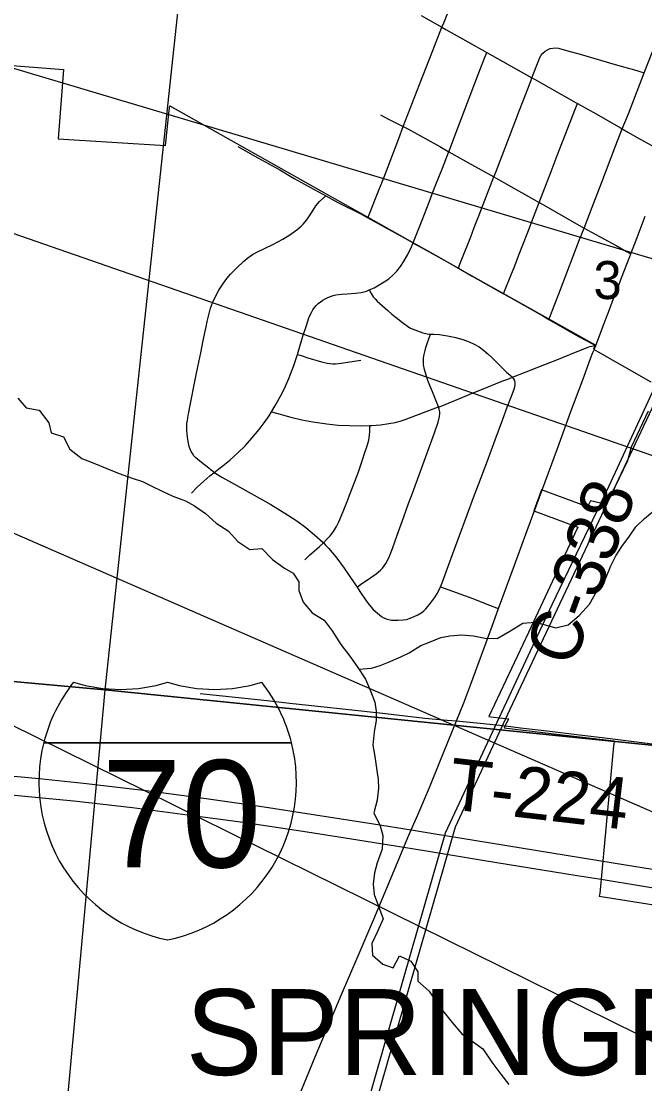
# Model space of a CAD drawing. Extents: x 0 to 34, y 0 to 22.
# Drawn here: x 7.893 to 8.581, y 15.624 to 16.796 of the extents above; entities that cross this region are included whole.
import ezdxf

# ---------------------------------------------------------------- set-up
doc = ezdxf.new("R2010")
doc.units = 0
for name, color, linetype in [('Default', 7, 'Continuous'), ('GM_X_City_Street', 7, 'Continuous'), ('GM_X_Corporation_Text', 7, 'Continuous'), ('GM_X_County_Road', 7, 'Continuous'), ('GM_X_County_Road_Text', 7, 'Continuous'), ('GM_X_Interstate_Location', 7, 'Continuous'), ('GM_X_Interstate_Route', 7, 'Continuous'), ('GM_X_Interstate_Shield', 7, 'Continuous'), ('GM_X_Minor_River', 7, 'Continuous'), ('GM_X_Rail_Line', 7, 'Continuous'), ('GM_X_Section', 7, 'Continuous'), ('GM_X_Section_Text', 7, 'Continuous'), ('GM_X_Township_Road', 7, 'Continuous'), ('GM_X_Township_Road_Text', 7, 'Continuous'), ('SC_Shading1', 7, 'Continuous'), ('SH_Text', 7, 'Continuous')]:
    doc.layers.add(name, color=color, linetype=linetype)

msp = doc.modelspace()

# ---------------------------------------------------------------- linework, layer by layer
at = {"layer": 'Default'}
for points in [[(8.9, 15.9657), (8.9, 17.0075), (8.0956, 17.09), (7.9848, 16.0585)], [(8.9, 14.9629), (8.9, 15.9657), (7.9848, 16.0585), (7.893, 15.0559), (8.8988, 14.9496)]]:
    msp.add_lwpolyline(points, close=True, dxfattribs=at)
at = {"layer": 'GM_X_City_Street'}
for points in [[(8.4747, 16.467), (8.4764, 16.4712), (8.4787, 16.477), (8.4876, 16.5001), (8.5087, 16.5551), (8.5136, 16.5677), (8.5177, 16.5782), (8.5243, 16.5955), (8.533, 16.6184), (8.5487, 16.6592), (8.5557, 16.677), (8.5624, 16.6938), (8.58, 16.739), (8.5893, 16.7631), (8.5993, 16.7891), (8.6027, 16.7971), (8.6074, 16.809), (8.6105, 16.8175), (8.6122, 16.8234), (8.6135, 16.8294), (8.6139, 16.8323), (8.6146, 16.8413), (8.6154, 16.8504), (8.616, 16.8562)], [(8.2752, 16.5791), (8.2768, 16.5832), (8.2837, 16.6003), (8.2927, 16.6231), (8.3004, 16.6433), (8.3093, 16.6665), (8.3142, 16.6795), (8.3244, 16.7063), (8.3322, 16.7261), (8.3466, 16.7635), (8.3568, 16.7893), (8.3591, 16.7947), (8.3627, 16.8031), (8.3654, 16.8086), (8.3701, 16.8163), (8.3737, 16.8212), (8.3776, 16.8258), (8.3819, 16.8301), (8.3856, 16.8334), (8.3882, 16.8354), (8.3896, 16.8365), (8.391, 16.8372), (8.3922, 16.8375)], [(8.3339, 16.8022), (8.3568, 16.7893), (8.361, 16.7868), (8.3855, 16.7731), (8.4062, 16.7614), (8.4561, 16.7332), (8.4588, 16.7317), (8.5049, 16.7056), (8.5063, 16.7049), (8.5268, 16.6935), (8.5538, 16.6781), (8.5557, 16.677), (8.562, 16.6735), (8.5755, 16.6657), (8.5916, 16.6569), (8.595, 16.6551), (8.598, 16.6535), (8.601, 16.6518), (8.607, 16.6485)], [(8.3749, 16.5234), (8.3767, 16.5278), (8.3824, 16.5426), (8.3849, 16.5488), (8.3885, 16.5581), (8.3924, 16.5682), (8.3974, 16.581), (8.4004, 16.5887), (8.4142, 16.6241), (8.4163, 16.6293), (8.4314, 16.6687), (8.4425, 16.6977), (8.4547, 16.7295), (8.4561, 16.7332), (8.4635, 16.7528), (8.4648, 16.7556), (8.4662, 16.7583), (8.4682, 16.7607), (8.4706, 16.7627), (8.4732, 16.7643), (8.4761, 16.7655), (8.4791, 16.7661), (8.4822, 16.7663), (8.4853, 16.766), (8.4943, 16.7636), (8.5092, 16.7593), (8.548, 16.7482), (8.5719, 16.7413), (8.5749, 16.7404), (8.58, 16.739)], [(8.3251, 16.5514), (8.327, 16.5562), (8.3351, 16.5762), (8.3426, 16.5962), (8.3457, 16.6044), (8.3493, 16.6137), (8.3573, 16.6338), (8.3641, 16.6511), (8.3644, 16.6518), (8.375, 16.6801), (8.3949, 16.7322), (8.4037, 16.7551), (8.4062, 16.7614)], [(8.4248, 16.4953), (8.4266, 16.4998), (8.4329, 16.5154), (8.4371, 16.526), (8.4413, 16.5371), (8.446, 16.5491), (8.4514, 16.5631), (8.4597, 16.5844), (8.4642, 16.596), (8.4774, 16.6302), (8.4839, 16.6476), (8.5042, 16.6994), (8.5063, 16.7049)], [(8.289, 16.6926), (8.297, 16.6881), (8.3081, 16.6826), (8.3142, 16.6795), (8.3191, 16.677), (8.3543, 16.6575), (8.3644, 16.6518), (8.3895, 16.6379), (8.4142, 16.6241), (8.4166, 16.6228), (8.4642, 16.596), (8.4688, 16.5934), (8.5054, 16.5723), (8.5136, 16.5677), (8.5216, 16.5632), (8.5489, 16.5483), (8.5604, 16.5419), (8.5652, 16.5394)]]:
    msp.add_lwpolyline(points, dxfattribs=at)
at = {"layer": 'GM_X_County_Road'}
msp.add_line((8.5234, 16.4305), (8.5246, 16.4334), dxfattribs=at)
for points in [[(8.5652, 16.5394), (8.5721, 16.5574), (8.5811, 16.5808)], [(8.5264, 16.4381), (8.5373, 16.4666), (8.5415, 16.4778), (8.5462, 16.49), (8.5508, 16.5018), (8.555, 16.5129), (8.5641, 16.5364), (8.5652, 16.5394)], [(8.4193, 16.1481), (8.4229, 16.1581), (8.4369, 16.196), (8.4507, 16.2341), (8.4842, 16.3245), (8.4991, 16.3654), (8.5121, 16.4004), (8.5207, 16.4238), (8.5234, 16.4305)], [(8.5246, 16.4334), (8.5255, 16.4357), (8.5264, 16.4381)], [(8.373, 16.0241), (8.3808, 16.0443), (8.3886, 16.0646), (8.4123, 16.1288), (8.4193, 16.1481)], [(8.2816, 15.8055), (8.3079, 15.8679), (8.3149, 15.8849), (8.3193, 15.8955), (8.323, 15.904), (8.3303, 15.9207), (8.3431, 15.9506), (8.3545, 15.9791), (8.373, 16.0241)], [(8.1707, 15.5377), (8.1766, 15.553), (8.1914, 15.5905), (8.1994, 15.6107), (8.217, 15.6538), (8.246, 15.7225), (8.2645, 15.7652), (8.2816, 15.8055)]]:
    msp.add_lwpolyline(points, dxfattribs=at)
at = {"layer": 'GM_X_Interstate_Route'}
for points in [[(7.8568, 15.966), (7.9124, 15.9606), (7.9613, 15.9556), (8.0305, 15.9476), (8.0943, 15.9389), (8.1559, 15.9303), (8.2172, 15.9208), (8.2813, 15.9108), (8.323, 15.904), (8.347, 15.9002), (8.4104, 15.8897), (8.5456, 15.8678), (8.6624, 15.8489), (8.7176, 15.8399), (8.8158, 15.824), (8.8737, 15.8145), (8.9, 15.8102)], [(7.7421, 15.9546), (7.777, 15.952), (7.8186, 15.949), (7.9003, 15.941), (7.9508, 15.936), (8.0154, 15.9286), (8.0761, 15.9208), (8.1375, 15.9124), (8.208, 15.902), (8.257, 15.8941), (8.3149, 15.8849), (8.3397, 15.8809), (8.4036, 15.8703), (8.5061, 15.8539), (8.5347, 15.8492)], [(8.5347, 15.8492), (8.7351, 15.8161), (8.8796, 15.7931), (8.9, 15.7898)]]:
    msp.add_lwpolyline(points, dxfattribs=at)
at = {"layer": 'GM_X_Interstate_Shield'}
for p, q in [((7.9176, 16.0002), (8.1909, 16.0002)), ((8.1909, 16.0002), (7.9176, 16.0002)), ((8.1909, 16.0002), (7.9176, 16.0002))]:
    msp.add_line(p, q, dxfattribs=at)
for centre, start, end in [((8.0898, 15.9567), 141.669, 165.8066), ((8.0024, 16.2366), 253.0091, 286.9909), ((8.1061, 16.2366), 253.0091, 286.9909), ((8.0187, 15.9567), 14.1934, 38.331), ((8.0898, 15.9567), 165.8066, 258.463), ((8.0187, 15.9567), 281.537, 14.1934)]:
    msp.add_arc(centre, 0.1776, start, end, dxfattribs=at)
at = {"layer": 'GM_X_Minor_River'}
for points in [[(7.889, 16.3801), (7.8983, 16.3694), (7.9127, 16.367), (7.9232, 16.3529), (7.9258, 16.3419), (7.9393, 16.3376), (7.9464, 16.3239), (7.9596, 16.3136), (7.9728, 16.3085), (7.9871, 16.3024), (8.0007, 16.297), (8.015, 16.2919), (8.0267, 16.2881), (8.0369, 16.283), (8.0475, 16.278), (8.0599, 16.2719), (8.0739, 16.2668), (8.0837, 16.2615), (8.0961, 16.253), (8.1077, 16.2423), (8.1209, 16.2339), (8.1318, 16.2221), (8.145, 16.2132), (8.1582, 16.2143), (8.1698, 16.2021), (8.183, 16.1925), (8.1928, 16.1871), (8.1988, 16.1776), (8.1991, 16.1681), (8.2039, 16.1552), (8.2137, 16.1434), (8.2268, 16.1353), (8.2358, 16.1235), (8.2452, 16.1086), (8.2553, 16.0957), (8.2639, 16.0831), (8.2725, 16.0701), (8.2781, 16.0572), (8.2829, 16.045), (8.2843, 16.0348), (8.2843, 16.0245), (8.2819, 16.012), (8.2807, 15.9976), (8.2828, 15.9851), (8.285, 15.9696), (8.2864, 15.9597), (8.2867, 15.9502), (8.2855, 15.9369), (8.2816, 15.923), (8.2887, 15.9085), (8.2916, 15.8979), (8.2908, 15.8827), (8.2854, 15.8676), (8.2826, 15.8566), (8.281, 15.8441), (8.2821, 15.8327)], [(8.2651, 16.0813), (8.279, 16.0822), (8.2885, 16.0852), (8.298, 16.0889), (8.3113, 16.0949), (8.3208, 16.0993), (8.3337, 16.1072), (8.3432, 16.1109), (8.3557, 16.1161), (8.3655, 16.118), (8.3784, 16.119), (8.3916, 16.1181), (8.4045, 16.1154), (8.4177, 16.1149), (8.4318, 16.1232), (8.4459, 16.1321), (8.4595, 16.1332), (8.4693, 16.1305), (8.4825, 16.1269), (8.4961, 16.1303), (8.5083, 16.1404), (8.5194, 16.1528), (8.5278, 16.1672), (8.5374, 16.1815), (8.5432, 16.1951), (8.5485, 16.2061), (8.5554, 16.2166), (8.5635, 16.2279), (8.5707, 16.2381), (8.5802, 16.2475), (8.5928, 16.2577)], [(8.2821, 15.8327), (8.2869, 15.8198), (8.2921, 15.8061), (8.2856, 15.7921), (8.2794, 15.7789), (8.2801, 15.766), (8.2917, 15.7561), (8.303, 15.7518), (8.3099, 15.765), (8.3224, 15.7592), (8.3302, 15.7474), (8.3302, 15.7372), (8.3426, 15.7261), (8.35, 15.7151), (8.3579, 15.7044), (8.368, 15.6918), (8.3789, 15.6792), (8.3887, 15.6723), (8.4019, 15.6627), (8.412, 15.6479), (8.4217, 15.6345), (8.4307, 15.6231)]]:
    msp.add_lwpolyline(points, dxfattribs=at)
at = {"layer": 'GM_X_Rail_Line'}
for points in [[(7.2798, 14.1), (7.3804, 14.2899), (7.4399, 14.3809), (7.5029, 14.451), (7.5671, 14.514), (7.6729, 14.6161), (7.8627, 14.7836), (7.9234, 14.8447), (7.9746, 14.9008), (8.0463, 14.9864), (8.1054, 15.083), (8.1652, 15.2252), (8.1826, 15.274), (8.2135, 15.3861), (8.2835, 15.6324), (8.3606, 15.9006), (8.4204, 16.0285), (8.4785, 16.1527), (8.5411, 16.2834), (8.5955, 16.4012), (8.7466, 16.719), (8.8431, 16.9243), (8.9, 17.0477)], [(8.6715, 16.5448), (8.4316, 16.0366), (8.3713, 15.9072), (8.1815, 15.2486), (8.1107, 15.0795), (8.0486, 14.9789), (7.9789, 14.8968), (7.9015, 14.815), (7.882, 14.794), (7.8474, 14.7064), (7.8234, 14.6409), (7.725, 14.3971), (7.6108, 14.1)]]:
    msp.add_lwpolyline(points, dxfattribs=at)
at = {"layer": 'GM_X_Section'}
for points in [[(7.0855, 17.1656), (8.0956, 17.09), (7.9848, 16.0585), (6.992, 16.1486)], [(6.992, 16.1486), (7.9848, 16.0585), (7.893, 15.0559), (6.9002, 15.1449)]]:
    msp.add_lwpolyline(points, close=True, dxfattribs=at)
at = {"layer": 'GM_X_Township_Road'}
for points in [[(8.1317, 16.6576), (8.1403, 16.6527), (8.1536, 16.645), (8.178, 16.6318), (8.1939, 16.6225), (8.2127, 16.6119), (8.2286, 16.6032)], [(8.1057, 16.2982), (8.1049, 16.2988), (8.1023, 16.3007), (8.0997, 16.3028), (8.0915, 16.309), (8.0877, 16.3123), (8.0853, 16.3144), (8.0832, 16.3166), (8.0816, 16.319), (8.0802, 16.3212), (8.0791, 16.3238), (8.0781, 16.3267), (8.0773, 16.3304), (8.0765, 16.3346), (8.0759, 16.3399), (8.0754, 16.3453), (8.0754, 16.3492), (8.0756, 16.3523), (8.076, 16.3554), (8.0769, 16.3615), (8.0775, 16.3644), (8.0787, 16.3705), (8.0855, 16.404), (8.0877, 16.4148), (8.0907, 16.4301), (8.0934, 16.4435), (8.0967, 16.4586), (8.098, 16.4646), (8.1, 16.4736), (8.1017, 16.4795), (8.1039, 16.4853), (8.1064, 16.4909), (8.1108, 16.4991), (8.1158, 16.507), (8.1195, 16.512), (8.1235, 16.5167), (8.1302, 16.5235), (8.1384, 16.5312), (8.1426, 16.5347), (8.1467, 16.5376), (8.1487, 16.539), (8.1533, 16.5416), (8.1701, 16.5497), (8.1812, 16.5554), (8.1892, 16.5602), (8.1967, 16.5656), (8.2015, 16.5696), (8.2037, 16.5718), (8.2076, 16.5767), (8.2128, 16.5844), (8.2178, 16.5923), (8.2218, 16.5971), (8.2286, 16.6032)], [(8.2286, 16.6032), (8.2421, 16.596), (8.2667, 16.5837), (8.2752, 16.5791)], [(8.2752, 16.5791), (8.3126, 16.5584), (8.3251, 16.5514)], [(8.2766, 16.4994), (8.2822, 16.5019), (8.2877, 16.5049), (8.293, 16.5082), (8.2981, 16.5118), (8.3028, 16.5158), (8.3071, 16.5203), (8.311, 16.5251), (8.3144, 16.5303), (8.319, 16.5386), (8.3232, 16.5469), (8.3251, 16.5514)], [(8.3251, 16.5514), (8.3288, 16.5493), (8.3499, 16.5374), (8.3633, 16.5301), (8.3749, 16.5234)], [(8.3749, 16.5234), (8.3901, 16.5148), (8.4248, 16.4953)], [(8.1976, 16.4283), (8.2035, 16.4484), (8.2073, 16.4602), (8.2101, 16.4686), (8.2115, 16.4719), (8.2128, 16.4747), (8.2143, 16.4774), (8.2162, 16.48), (8.2182, 16.4823), (8.2204, 16.4845), (8.2228, 16.4865), (8.2254, 16.4882), (8.2281, 16.4898), (8.2309, 16.4912), (8.2338, 16.4923), (8.2367, 16.4932), (8.2398, 16.4939), (8.246, 16.4946), (8.2522, 16.4951), (8.2615, 16.496), (8.2676, 16.4967), (8.2707, 16.4973), (8.2737, 16.4981), (8.2766, 16.4994)], [(8.2766, 16.4994), (8.2787, 16.4956), (8.281, 16.492), (8.283, 16.4895), (8.2855, 16.4869), (8.2971, 16.4766), (8.3016, 16.4729), (8.3063, 16.4689), (8.3134, 16.4634), (8.3187, 16.4594), (8.3213, 16.4578), (8.3241, 16.4564), (8.3298, 16.4542), (8.3357, 16.4523), (8.3406, 16.4512), (8.3442, 16.4507)], [(8.4248, 16.4953), (8.4304, 16.4922), (8.4681, 16.4708), (8.4747, 16.467)], [(8.4747, 16.467), (8.4971, 16.4541), (8.5083, 16.4477), (8.5237, 16.4395), (8.5264, 16.4381)], [(8.3531, 16.3704), (8.3517, 16.3742), (8.3494, 16.3798), (8.3483, 16.3827), (8.3435, 16.394), (8.3413, 16.3997), (8.3393, 16.4056), (8.3377, 16.4116), (8.3366, 16.4168), (8.3364, 16.4208), (8.3365, 16.4237), (8.3369, 16.4268), (8.3382, 16.4328), (8.339, 16.4358), (8.3409, 16.4415), (8.3419, 16.4444), (8.3442, 16.4507)], [(8.3442, 16.4507), (8.3448, 16.4506), (8.3478, 16.4505), (8.354, 16.4502), (8.3631, 16.449), (8.3721, 16.4471), (8.381, 16.4445), (8.3868, 16.4423), (8.3924, 16.4398), (8.3977, 16.4366), (8.4027, 16.433), (8.4074, 16.429), (8.4119, 16.4248), (8.4229, 16.4138), (8.4279, 16.4089), (8.4319, 16.4054), (8.4346, 16.4031)], [(8.1688, 16.3651), (8.1726, 16.3713), (8.1801, 16.3849), (8.1843, 16.3933), (8.1881, 16.4018), (8.1936, 16.4162), (8.1976, 16.4283)], [(8.1976, 16.4283), (8.2027, 16.4267), (8.209, 16.4247), (8.224, 16.4202), (8.2302, 16.4187), (8.2333, 16.4182), (8.2364, 16.4179), (8.2395, 16.4179), (8.2458, 16.4186), (8.2675, 16.422)], [(8.4346, 16.4031), (8.4498, 16.4091), (8.4637, 16.4145), (8.4836, 16.4225), (8.5041, 16.4308), (8.5181, 16.4362), (8.5199, 16.4369), (8.522, 16.4374), (8.5235, 16.4377), (8.5264, 16.4381)], [(8.3531, 16.3704), (8.354, 16.3707), (8.3712, 16.3776), (8.3912, 16.3859), (8.3997, 16.3894), (8.424, 16.3991), (8.4294, 16.4011), (8.4346, 16.4031)], [(8.3551, 16.1721), (8.357, 16.1764), (8.3643, 16.1968), (8.3685, 16.2078), (8.3845, 16.2514), (8.3917, 16.2705), (8.3972, 16.2849), (8.4069, 16.3109), (8.4155, 16.334), (8.4238, 16.3569), (8.4288, 16.3701), (8.4344, 16.384), (8.4369, 16.3911), (8.4376, 16.3946), (8.4376, 16.3966), (8.4371, 16.3995), (8.4361, 16.4013), (8.4346, 16.4031)], [(8.2632, 16.1718), (8.2675, 16.1749), (8.2726, 16.1784), (8.2794, 16.1831), (8.2843, 16.1865), (8.289, 16.1905), (8.2911, 16.1928), (8.293, 16.1952), (8.2948, 16.1978), (8.2964, 16.2004), (8.299, 16.2058), (8.3024, 16.2143), (8.3075, 16.2289), (8.3147, 16.2493), (8.3199, 16.2638), (8.3242, 16.2754), (8.3327, 16.2985), (8.3402, 16.3188), (8.3486, 16.342), (8.3525, 16.3537), (8.3541, 16.3597), (8.3546, 16.3628), (8.3544, 16.3652), (8.3538, 16.3681), (8.3531, 16.3704)], [(8.2773, 16.35), (8.2796, 16.3501), (8.2889, 16.3508), (8.2981, 16.352), (8.3052, 16.3533), (8.3106, 16.3547), (8.3162, 16.3565), (8.3365, 16.3642), (8.3531, 16.3704)], [(8.1057, 16.2982), (8.1069, 16.2991), (8.1106, 16.302), (8.1155, 16.3058), (8.1227, 16.3118), (8.1315, 16.3198), (8.1396, 16.3276), (8.1471, 16.336), (8.1551, 16.3454), (8.1608, 16.3529), (8.1661, 16.3606), (8.1688, 16.3651)], [(8.1688, 16.3651), (8.1783, 16.3624), (8.1902, 16.359), (8.2023, 16.3562), (8.2145, 16.3539), (8.2299, 16.3517), (8.2423, 16.3505), (8.2547, 16.3498), (8.2672, 16.3497), (8.2773, 16.35)], [(8.226, 16.2207), (8.2302, 16.2249), (8.2337, 16.2284), (8.2372, 16.2331), (8.2404, 16.2384), (8.2431, 16.2439), (8.248, 16.2553), (8.2529, 16.2679), (8.2549, 16.2733), (8.2606, 16.2882), (8.2643, 16.2978), (8.2695, 16.3131), (8.2715, 16.319), (8.2745, 16.3277), (8.2761, 16.3337), (8.2767, 16.3367), (8.277, 16.3397), (8.2771, 16.3425), (8.2773, 16.35)], [(8.0806, 16.2754), (8.087, 16.2821), (8.0942, 16.2886), (8.1009, 16.2943), (8.1057, 16.2982)], [(8.1057, 16.2982), (8.1142, 16.2931), (8.1248, 16.2871), (8.1679, 16.263), (8.1863, 16.2516), (8.1966, 16.2447), (8.2066, 16.2373), (8.2162, 16.2295), (8.2254, 16.2213), (8.226, 16.2207)], [(8.2056, 16.202), (8.2109, 16.2068), (8.2218, 16.2167), (8.226, 16.2207)], [(8.226, 16.2207), (8.2288, 16.2178), (8.2318, 16.2146), (8.2396, 16.205), (8.249, 16.1927), (8.2561, 16.1825), (8.2632, 16.1718)], [(8.2632, 16.1718), (8.2663, 16.167), (8.2732, 16.1567), (8.277, 16.1518), (8.2811, 16.1471), (8.2856, 16.1429), (8.2879, 16.141), (8.2903, 16.1394), (8.2927, 16.1379), (8.2954, 16.1368), (8.2984, 16.1359), (8.301, 16.1354), (8.3037, 16.1352), (8.3084, 16.1352), (8.314, 16.1357), (8.3177, 16.1362), (8.3216, 16.1374), (8.3262, 16.1392), (8.3303, 16.1412), (8.3345, 16.1438), (8.3369, 16.1457), (8.3391, 16.1477), (8.3431, 16.1524), (8.3485, 16.16), (8.3518, 16.1652), (8.3546, 16.1707), (8.3551, 16.1721)], [(8.3551, 16.1721), (8.3592, 16.1706), (8.3907, 16.159), (8.4026, 16.1545), (8.4094, 16.1519), (8.4169, 16.149), (8.4193, 16.1481)], [(8.0902, 16.0546), (8.1642, 16.0467), (8.189, 16.0439), (8.22, 16.0406), (8.2541, 16.0368), (8.2944, 16.0323), (8.3378, 16.0272), (8.3625, 16.025), (8.373, 16.0241)], [(8.373, 16.0241), (8.3876, 16.0229), (8.3988, 16.0217), (8.4271, 16.0186), (8.4436, 16.0167), (8.4759, 16.0128), (8.5056, 16.0091), (8.5363, 16.0054), (8.6003, 15.9975), (8.6013, 15.9974)]]:
    msp.add_lwpolyline(points, dxfattribs=at)
at = {"layer": 'SC_Shading1'}
for points in [[(7.8732, 16.7475), (7.9395, 16.7425), (7.9334, 16.6662), (8.052, 16.6588), (8.056, 16.6972), (8.0565, 16.7023), (8.229, 16.6054), (8.2749, 16.5796), (8.3247, 16.5517), (8.3248, 16.5516), (8.3531, 16.5358), (8.3746, 16.5236), (8.5258, 16.4388), (8.524, 16.4341), (8.529, 16.4313), (8.5872, 16.398)], [(8.5844, 16.3657), (8.5655, 16.3261), (8.5616, 16.3109), (8.5384, 16.2628), (8.5205, 16.267), (8.5173, 16.2603), (8.4667, 16.279), (8.4582, 16.2559), (8.5067, 16.238), (8.4866, 16.195), (8.4521, 16.1216), (8.4085, 16.0289), (8.4135, 16.0284), (8.4205, 16.0276), (8.4304, 16.0266), (8.4255, 16.0164), (8.4893, 16.009), (8.4931, 16.0086), (8.5467, 16.0023), (8.5463, 15.9986), (8.5461, 15.9967), (8.5361, 15.8899), (8.5308, 15.834), (8.5303, 15.8311), (8.8452, 15.7811)]]:
    msp.add_lwpolyline(points, dxfattribs=at)
at = {"layer": 'SH_Text'}
for points in [[(9.3277, 15.6016), (4.1983, 17.8389), (9.3277, 15.3062)], [(9.3042, 16.3207), (4.2062, 17.84), (9.3042, 16.0683)]]:
    msp.add_lwpolyline(points, close=True, dxfattribs=at)

# ---------------------------------------------------------------- texts
at = {"layer": 'GM_X_Corporation_Text'}
msp.add_text('SPRINGFIELD', height=0.094697, rotation=0, dxfattribs=at).set_placement((8.0743, 15.6337))
at = {"layer": 'GM_X_County_Road_Text'}
msp.add_text('C-338', height=0.05682, rotation=69.9238, dxfattribs=at).set_placement((8.5009, 16.0816))
at = {"layer": 'GM_X_Interstate_Location'}
for s in ['-', '.', ',']:
    msp.add_text(s, height=0.000189, dxfattribs=at).set_placement((8.0542, 15.9247))
msp.add_text('70', height=0.000189, rotation=0, dxfattribs=at).set_placement((8.0155, 15.8855))
at = {"layer": 'GM_X_Interstate_Shield'}
msp.add_text('70', height=0.11837, dxfattribs=at).set_placement((7.9815, 15.8626))
at = {"layer": 'GM_X_Section_Text'}
msp.add_text('3', height=0.0419, rotation=0, dxfattribs=at).set_placement((8.5239, 16.4894))
at = {"layer": 'GM_X_Township_Road_Text'}
msp.add_text('T-224', height=0.05682, rotation=353.3237, dxfattribs=at).set_placement((8.3622, 15.9273))

doc.saveas('drawing.dxf')
